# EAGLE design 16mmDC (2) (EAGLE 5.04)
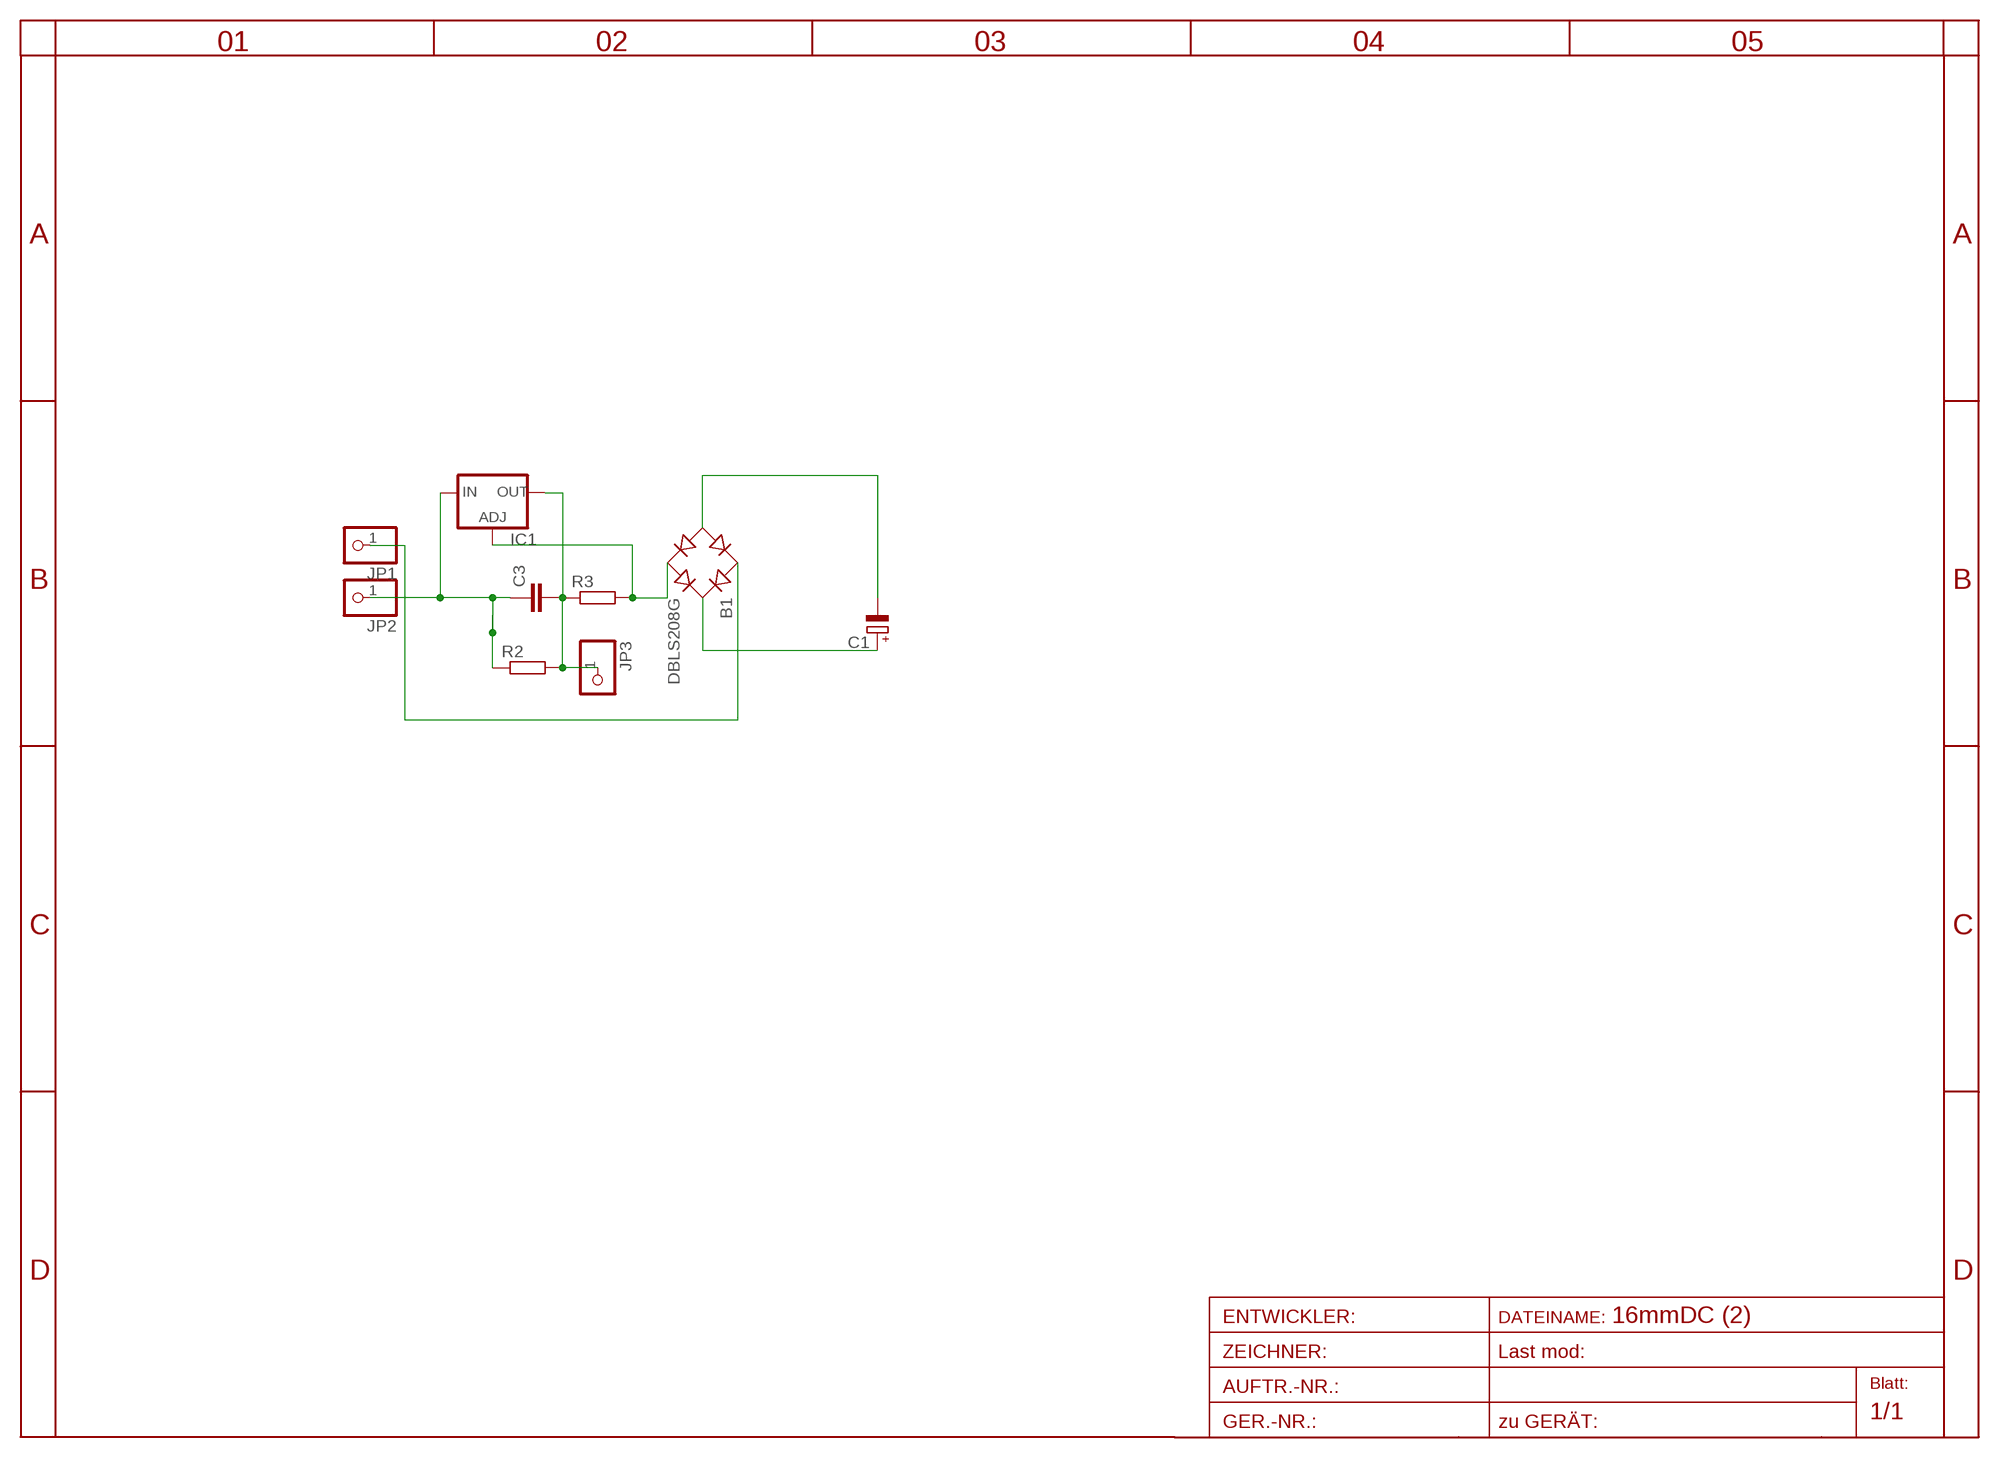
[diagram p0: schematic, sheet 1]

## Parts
B1  DBLS208G  [DBS]
C1  CPOL-EUE5-8.5  [E5-8,5]
C3  C-EU102-064X133  [C102-064X133]
IC1  LM317LZ  [317L]
JP1  PINHD-1X1  [1X01]
JP2  PINHD-1X1  [1X01]
JP3  PINHD-1X1  [1X01]
R2  R-EU_R1206  [R1206]
R3  R-EU_R1206  [R1206]

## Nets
AC: B1.AC1 JP1.1
AC+: C3.1 IC1.3(IN) JP2.1 R2.1
N$1: C3.2 IC1.2(OUT) JP3.1 R2.2 R3.1
N$2: B1.+ C1.+
N$5: B1.AC2 IC1.1(ADJ) R3.2
N$9: B1.- C1.-

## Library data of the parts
B1 = rectifier:DB?*G: Single Phase 1.0 AMP Glass Passivated Bridge Rectifier Taiwan Semiconductor Co.,Ltd. - TSC Source: http://www.taiwansemi.com/TSCbig5/ezcatfiles/cust/img/img/db101g.pdf http://www.ts.com.tw/db/pictures/modules/PDT/PDT060207001/DBLS201G.pdf
C1 = rcl-2:CPOL-EU: POLARIZED CAPACITOR, European symbol
C3 = rcl:C-EU: CAPACITOR, European symbol
IC1 = v-reg-3:LM317L: Adjustable Voltage Regulator, 1.2V to 37V, 100mA
JP1-JP3 = pinhead:PINHD-1X1: PIN HEADER
R2 R3 = rcl:R-EU_: RESISTOR, European symbol

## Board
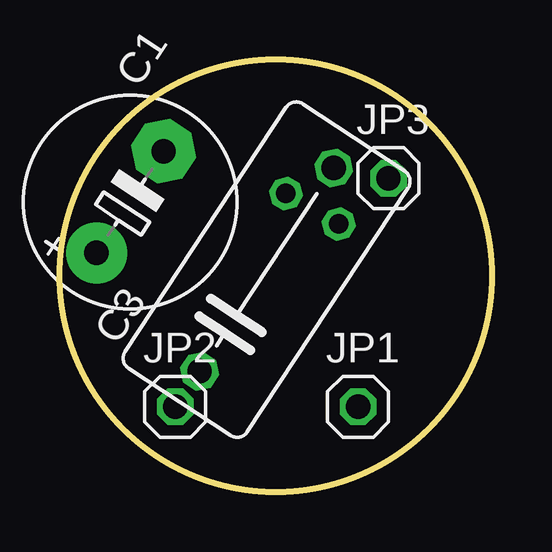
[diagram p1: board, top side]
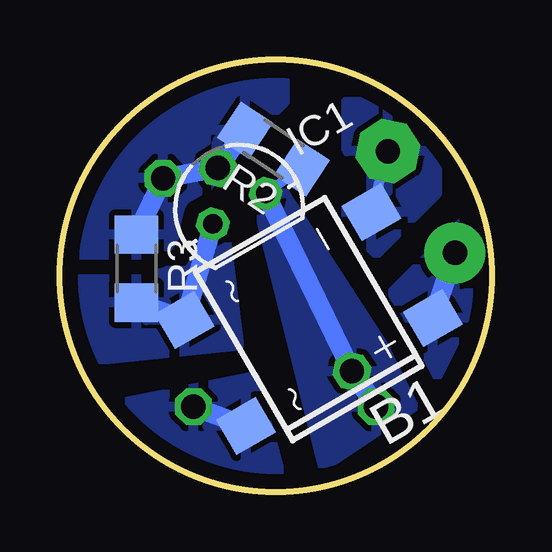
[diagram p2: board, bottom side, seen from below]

Size 18 x 18 mm. Coordinates in mm from the lower left corner, seen from the top.
Outline: circle at 9,9 radius 9
Copper layers (1*16): Top 0.035mm / dielectric 1.5mm / Bottom 0.035mm
Design rules "default *": minimum track width 10mil, minimum drill 24mil, track to track 8mil, track to pad 8mil, pad to pad 8mil, via to via 8mil, smd to smd 8mil, copper to edge 4mil, drill to drill 8mil, minimum pad ring 10mil, minimum via ring 8mil, stop-mask expansion 4mil, vias tented up to drill 0mil, thermal gap 10mil

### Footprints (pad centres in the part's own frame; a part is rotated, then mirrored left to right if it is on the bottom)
DBS = smd 1.7 x 1.9: + -2.55,-4.5; - 2.55,-4.5; AC1 -2.55,4.5; AC2 2.55,4.5
E5-8,5 = drill 1.016 pad 2.54 round: + -2.54,0 | drill 1.016 pad 2.54 octagon: - 2.54,0
C102-064X133 = drill 1.016 octagon: 1 -5.08,0; 2 5.08,0
317L = drill 0.813 octagon: 1 -1.27,0; 2 0,1.905; 3 1.27,0
1X01 = drill 1.016 octagon: 1 0,0
R1206 = smd 1.6 x 1.803: 1 -1.422,0; 2 1.422,0

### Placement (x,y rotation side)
B1  7.62,7.19 120 bottom
C1  2.93,12.07 56.6 top
C3  8.62,9.26 56.6 top
IC1  10.53,11.79 30 bottom
JP1  12.43,3.54 0 top
JP2  4.81,3.54 0 top
JP3  13.7,13.06 0 top
R2  9.1,14.28 146.6 bottom
R3  14.81,9.3 270 bottom

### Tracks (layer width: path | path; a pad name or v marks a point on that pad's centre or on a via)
AC
  Bottom 0.813: B1.AC1 JP1.1
  pour Bottom (isolate 0.61, rank 2): 9.89,4.81 16.24,3.54 9.89,-0.27 8.62,0.05
AC+
  Bottom 0.406: IC1.3 R2.1
  Bottom 0.813: JP2.1 C3.1 IC1.3
  pour Bottom (isolate 0.61): 4.49,6.08 8.62,12.43 9.89,12.43 7.03,1 3.22,3.54
N$1
  Bottom 0.406: IC1.2 C3.2
  Bottom 0.813: R2.2 C3.2 JP3.1 R3.1
  pour Bottom (isolate 0.61, rank 2): 8.62,17.51 13.7,16.24 17.51,11.16 17.51,9.89 13.7,9.89 11.16,13.7 8.62,16.24
N$2
  Bottom 0.813: B1.+ C1.+
  pour Bottom (isolate 0.61, rank 3): -0.27,9.89 2.27,4.81 3.54,7.35 4.17,8.3 1.32,11.16
N$5
  Bottom 0.813: IC1.1 B1.AC2 R3.2
  pour Bottom (isolate 0.61, rank 3): 11.16,11.16 10.53,6.08 16.56,5.45 17.19,8.94
N$9
  Bottom 0.406: B1.- C1.-
  pour Bottom (isolate 0.61, rank 3): 2.27,14.97 3.54,16.24 6.08,16.24 6.08,11.16 4.81,9.89 2.27,12.43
